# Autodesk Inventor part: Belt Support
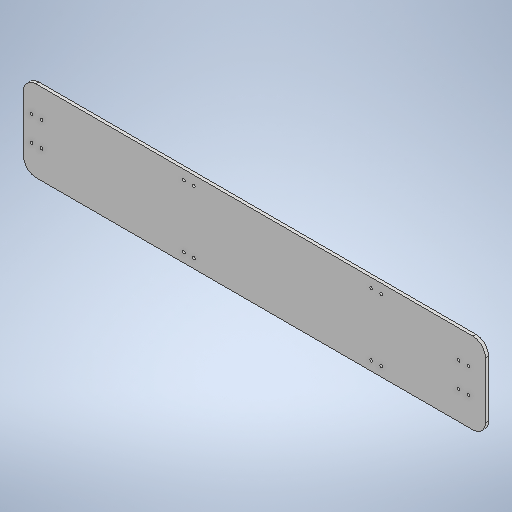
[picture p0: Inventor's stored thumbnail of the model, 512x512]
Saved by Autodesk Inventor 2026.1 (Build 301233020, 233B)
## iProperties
Created: 2026-10
Part Number: Belt Support
Material: Generic
Document SubType Name: Modeling
Designer: hp
Density: 1 g/cm^3
Appearance: Default
Author: hp
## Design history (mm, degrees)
sketch "Sketch1"
  geometry: L1 (0, 0)-(740, 0); L2 (740, 0)-(740, 130); L3 (740, 130)-(0, 130); L4 (0, 130)-(0, 0)
  constraints: 8 end point, 2 parallel, 1 horizontal, 1 perpendicular
  dimensions: "d0" = 740 distance of L3.end L2.end; "d1" = 130 distance of L2.end L1.end
extrude "Extrusion1" new body sketch "Sketch1" distance "d2" = 5; taper "d3" = 0 deg
fillet "Fillet1" dims "d4" = 20
sketch "Sketch2"
  geometry: 8 further points
hole "Hole1" sketch "Sketch2" at (-713, 85), (-697, 85), (-713, 45), (-697, 45), (-29, 85), (-29, 45), (-13, 45), (-13, 85) diameter "d5" = 4.5; stored, may be unused: countersink angle "d9" = 90 deg, drill point angle "d11" = 0 deg; dims "d6" = 6, "d7" = 4, "d8" = 2, "d10" = 8
sketch "Sketch3"
  geometry: 16 further points
hole "Hole2" sketch "Sketch3" at (573, 15), (557, 15), (273, 15), (257, 15), (573, 115), (557, 115), (273, 115), (257, 115), (273, 755), (257, 755), (257, 655), (273, 655)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 diameter "d12" = 4.5; stored, may be unused: countersink angle "d16" = 90 deg, drill point angle "d18" = 0 deg; dims "d13" = 6, "d14" = 4, "d15" = 2, "d17" = 8
body "Solid1"
